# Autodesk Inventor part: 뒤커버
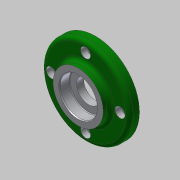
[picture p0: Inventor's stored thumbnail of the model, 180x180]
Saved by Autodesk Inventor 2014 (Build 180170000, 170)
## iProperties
Created: 2019-01
Part Number: 뒤커버
Material: 알루미늄 6061
Document SubType Name: Modeling
Designer: mduedu
Density: 1 g/cm^3
Appearance: Aluminum - Flat
Author: mduedu
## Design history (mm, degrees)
sketch "스케치1"
  geometry: L1 (0, 0)-(6, 0); L2 (6, 0)-(6, 20); L3 (6, 20)-(0, 20); L4 (0, 20)-(0, 0); L5 (6, 0)-(14, 0); L6 (14, 0)-(14, 35); L7 (14, 35)-(6, 35); L8 (6, 35)-(6, 0); L9 (14, 0)-(19, 0); L10 (19, 0)-(19, 20); L11 (19, 20)-(14, 20); L12 (14, 20)-(14, 0)
  constraints: 24 end point, 6 parallel, 3 horizontal, 3 perpendicular
  dimensions: "d6" = 70 diameter of L7 L5; "d8" = 40 diameter of L3 L1; "d9" = 40 diameter of L11 L9; "d10" = 5 distance of L10.end L11.end; "d11" = 6 distance of L2.end L3.end; "d12" = 19 distance between parallel lines of L4 L10; "d13" = 8 distance of L6.end L7.end (derived)
revolve "회전1" sketch "스케치1" stored, may be unused: angle "d5" = 90 deg
sketch "스케치2" dims "d14" = 55
  geometry: 7 further points
  constraints: 2 coincident, 2 vertical alignment, 7 other
  dimensions: "d17" = 360 deg dimension on point (0, 0) point (0, 27.5) (derived)
sketch "스케치3"
  geometry: 4 further points
  constraints: 4 other
hole "구멍1" sketch "스케치3" at (0, 27.5), (-27.5, 0), (27.5, 0), (0, -27.5) diameter "d19" = 4.5; stored, may be unused: countersink angle "d23" = 90 deg, drill point angle "d25" = 0 deg; dims "d20" = 6, "d21" = 8, "d22" = 4.6, "d24" = 8
fillet "모깎기1" dims "d26" = 3
sketch "스케치4"
  geometry: C1 r 9.5 at (0, 0); 1 further point
  constraints: 1 centre point, 1 coincident
  dimensions: "d27" = 19 diameter of C1
extrude "돌출1" cut sketch "스케치4" stored distance "d28" = 10; taper "d29" = 0 deg
sketch "스케치5"
  geometry: C1 r 15 at (0, 0); 1 further point
  constraints: 1 centre point, 1 coincident
  dimensions: "d31" = 30 diameter of C1
extrude "돌출2" cut sketch "스케치5" distance "d32" = 8.3; taper "d33" = 0 deg
chamfer "모따기1" distance "d34" = 0.8; stored, may be unused: second distance "d35" = 2, angle "d36" = 30 deg
fillet "모깎기2" dims "d37" = 3
fillet "모깎기3" dims "d38" = 0.5
sketch "스케치6"
  geometry: C1 r 16.5 at (0, 0); 1 further point
  constraints: 1 centre point, 1 coincident
  dimensions: "d39" = 33 diameter of C1
extrude "돌출3" cut sketch "스케치6" distance "d40" = 5; taper "d41" = 0 deg
fillet "모깎기4" dims "d42" = 3
chamfer "모따기2" distance "d43" = 1; stored, may be unused: second distance "d44" = 2, angle "d45" = 30 deg
node "솔리드1"
